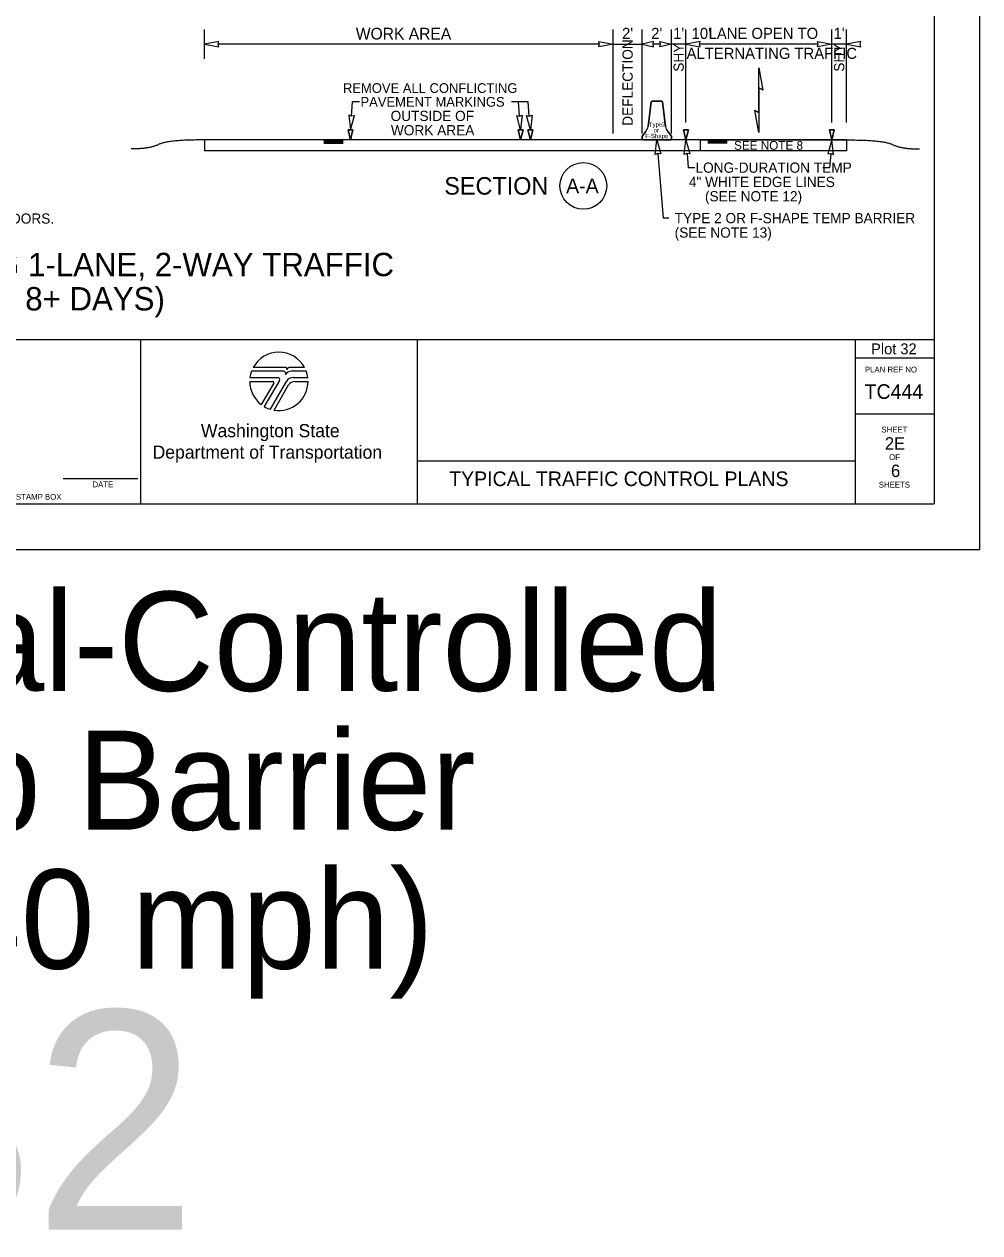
# Model space of a CAD drawing. Extents: x 99976 to 100136, y 99905 to 100011.
# Drawn here: x 100029.51 to 100036.06, y 99905.01 to 99913.29 of the extents above; entities that cross this region are included whole.
import ezdxf

# ---------------------------------------------------------------- set-up
doc = ezdxf.new("R2010")
doc.units = 0
for name, color, linetype in [('SH_DE_DetailHeading1Text', 7, 'Continuous'), ('SH_GI_GeneralNotesBodyText', 7, 'Continuous'), ('SH_GI_PlotLimits', 7, 'Continuous'), ('SH_GI_SheetBorder', 7, 'Continuous'), ('SH_GI_SheetLocationText', 7, 'Continuous'), ('SH_GI_SheetTextInCells', 7, 'Continuous'), ('SH_GI_TitleBlockText', 7, 'Continuous'), ('SH_GI_WSDOTLogo', 7, 'Continuous'), ('TR_WZ_BarrierDoubleFaceElev', 7, 'Continuous'), ('TR_WZ_WorkZoneDetails', 7, 'Continuous'), ('TR_WZ_WorkZoneTextCurrent', 7, 'Continuous')]:
    doc.layers.add(name, color=color, linetype=linetype)

msp = doc.modelspace()

# ---------------------------------------------------------------- linework, layer by layer
at = {"layer": 'SH_GI_PlotLimits'}
msp.add_lwpolyline([(100019.0625, 99909.6875), (100036.0625, 99909.6875), (100036.0625, 99920.6875), (100019.0625, 99920.6875)], close=True, dxfattribs=at)
at = {"layer": 'SH_GI_SheetBorder'}
for p, q in [((100035.75, 99920.375), (100035.75, 99910)), ((100020, 99911.1259), (100035.75, 99911.1259)), ((100030.3089, 99911.1259), (100030.3089, 99910)), ((100032.2055, 99911.1259), (100032.2055, 99910)), ((100035.2079, 99911.1259), (100035.2079, 99910)), ((100035.2079, 99911.0008), (100035.75, 99911.0008)), ((100035.2079, 99910.6176), (100035.75, 99910.6176)), ((100032.2055, 99910.2955), (100035.2079, 99910.2955)), ((100029.7797, 99910.1733), (100030.2914, 99910.1733)), ((100020, 99910), (100035.75, 99910))]:
    msp.add_line(p, q, dxfattribs=at)
at = {"layer": 'SH_GI_WSDOTLogo'}
for p, q in [((100031.059, 99910.8661), (100031.2496, 99910.8661)), ((100031.2894, 99910.9094), (100031.0697, 99910.9094)), ((100031.303, 99910.9354), (100031.0815, 99910.9354)), ((100031.433, 99910.9354), (100031.3351, 99910.9354)), ((100031.343, 99910.9094), (100031.3429, 99910.9094)), ((100031.4448, 99910.9094), (100031.343, 99910.9094)), ((100031.3558, 99910.8661), (100031.4555, 99910.8661)), ((100031.0572, 99910.84), (100031.2148, 99910.84)), ((100031.222, 99910.8277), (100031.1364, 99910.6807)), ((100031.261, 99910.8464), (100031.1567, 99910.6672)), ((100031.1989, 99910.6487), (100031.3089, 99910.839)), ((100031.2244, 99910.6428), (100031.3242, 99910.8156)), ((100031.3655, 99910.8394), (100031.4572, 99910.8394))]:
    msp.add_line(p, q, dxfattribs=at)
for centre, radius, start, end in [((100031.2572, 99910.84), 0.2, 28.47865, 151.53204), ((100031.2572, 99910.84), 0.2, 159.69598, 172.50569), ((100031.2497, 99910.853), 0.0131, 329.76834, 90), ((100031.2894, 99910.8946), 0.0148, 327.8418, 89.99855), ((100031.3429, 99910.861), 0.0484, 89.99529, 147.82376), ((100031.303, 99910.9263), 0.00903, 329.87418, 90.00328), ((100031.3558, 99910.8119), 0.0542, 90, 149.99738), ((100031.3352, 99910.9066), 0.0287, 90.00721, 148.16763), ((100031.2572, 99910.84), 0.2, 7.49431, 20.29406), ((100031.2572, 99910.84), 0.2, 179.99864, 232.84327), ((100031.2149, 99910.8318), 0.0082, 329.74356, 90), ((100031.2572, 99910.84), 0.2, 260.54554, 359.80857), ((100031.3654, 99910.7918), 0.0476, 90, 150.05432), ((100031.2572, 99910.84), 0.2, 239.79292, 253.0448)]:
    msp.add_arc(centre, radius, start, end, dxfattribs=at)
at = {"layer": 'TR_WZ_BarrierDoubleFaceElev'}
for p, q in [((100033.8083, 99912.7548), (100033.8145, 99912.761)), ((100033.8145, 99912.761), (100033.8083, 99912.7548)), ((100033.8145, 99912.761), (100033.8812, 99912.761)), ((100033.8812, 99912.761), (100033.8145, 99912.761)), ((100033.8812, 99912.761), (100033.8875, 99912.7548)), ((100033.8875, 99912.7548), (100033.8812, 99912.761)), ((100033.7885, 99912.586), (100033.8083, 99912.7548)), ((100033.8083, 99912.7548), (100033.7885, 99912.586)), ((100033.8875, 99912.7548), (100033.9073, 99912.586)), ((100033.9073, 99912.586), (100033.8875, 99912.7548)), ((100033.7479, 99912.5194), (100033.7729, 99912.5527)), ((100033.7729, 99912.5527), (100033.7479, 99912.5194)), ((100033.7479, 99912.5006), (100033.7479, 99912.5194)), ((100033.7479, 99912.5194), (100033.7479, 99912.5006)), ((100033.9229, 99912.5527), (100033.9479, 99912.5194)), ((100033.9479, 99912.5194), (100033.9229, 99912.5527)), ((100033.9479, 99912.5194), (100033.9479, 99912.5006)), ((100033.9479, 99912.5006), (100033.9479, 99912.5194)), ((100033.7541, 99912.4944), (100033.7479, 99912.5006)), ((100033.7479, 99912.5006), (100033.7541, 99912.4944)), ((100033.9416, 99912.4944), (100033.7541, 99912.4944)), ((100033.7541, 99912.4944), (100033.9416, 99912.4944)), ((100033.9479, 99912.5006), (100033.9416, 99912.4944)), ((100033.9416, 99912.4944), (100033.9479, 99912.5006))]:
    msp.add_line(p, q, dxfattribs=at)
for centre, start, end in [((100033.7071, 99912.6039), 322.1243, 347.64603), ((100033.7071, 99912.6039), 322.1243, 347.64603), ((100033.9887, 99912.6039), 192.35397, 217.8757), ((100033.9887, 99912.6039), 192.35397, 217.8757)]:
    msp.add_arc(centre, 0.0833, start, end, dxfattribs=at)
at = {"layer": 'TR_WZ_WorkZoneDetails'}
for p, q in [((100030.7479, 99913.0504), (100030.7479, 99913.2504)), ((100033.5479, 99912.5394), (100033.5479, 99913.2504)), ((100033.7479, 99912.5394), (100033.7479, 99913.2504)), ((100033.9479, 99912.5394), (100033.9479, 99913.2504)), ((100034.0479, 99912.6142), (100034.0479, 99913.2504)), ((100035.0479, 99912.6142), (100035.0479, 99913.2504)), ((100035.1479, 99912.6142), (100035.1479, 99913.2504)), ((100033.4542, 99913.1504), (100030.8416, 99913.1504)), ((100033.5479, 99913.1504), (100033.7479, 99913.1504)), ((100033.8729, 99913.1504), (100033.8229, 99913.1504)), ((100034.0479, 99913.1504), (100033.9479, 99913.1504)), ((100034.9542, 99913.1504), (100034.1416, 99913.1504)), ((100035.1479, 99913.1504), (100035.0479, 99913.1504)), ((100034.5479, 99912.8508), (100034.5479, 99912.682)), ((100034.5479, 99912.682), (100034.5479, 99912.8508)), ((100031.7553, 99912.6576), (100031.763, 99912.7552)), ((100031.8092, 99912.7552), (100031.763, 99912.7552)), ((100032.966, 99912.7552), (100032.8531, 99912.7552)), ((100032.9071, 99912.6576), (100032.8993, 99912.7552)), ((100032.9737, 99912.6576), (100032.966, 99912.7552)), ((100030.7479, 99912.4944), (100030.7479, 99912.4194)), ((100035.1479, 99912.4944), (100030.7479, 99912.4944)), ((100031.5649, 99912.4891), (100031.6979, 99912.4891)), ((100031.5649, 99912.4835), (100031.6979, 99912.4835)), ((100031.5649, 99912.4779), (100031.6979, 99912.4779)), ((100031.5649, 99912.4726), (100031.6979, 99912.4726)), ((100034.3309, 99912.4887), (100034.1979, 99912.4887)), ((100034.3309, 99912.4831), (100034.1979, 99912.4831)), ((100034.3309, 99912.4774), (100034.1979, 99912.4774)), ((100034.3309, 99912.4722), (100034.1979, 99912.4722)), ((100035.1479, 99912.4944), (100035.1479, 99912.4194)), ((100035.1479, 99912.4194), (100030.7479, 99912.4194)), ((100033.8553, 99912.4009), (100033.8906, 99911.9574)), ((100034.0553, 99912.4009), (100034.0631, 99912.3034)), ((100035.0404, 99912.4009), (100035.0327, 99912.3034)), ((100034.1092, 99912.3034), (100034.0631, 99912.3034)), ((100035.0327, 99912.3034), (100034.9865, 99912.3034)), ((100033.9306, 99911.9574), (100033.8906, 99911.9574))]:
    msp.add_line(p, q, dxfattribs=at)
for points in [[(100030.7479, 99913.1504), (100030.8461, 99913.1312), (100030.8416, 99913.1504), (100030.8461, 99913.1697)], [(100033.5479, 99913.1504), (100033.4496, 99913.1312), (100033.4542, 99913.1504), (100033.4496, 99913.1697)], [(100033.7479, 99913.1504), (100033.8265, 99913.1312), (100033.8229, 99913.1504), (100033.8265, 99913.1697)], [(100033.9479, 99913.1504), (100033.8693, 99913.1312), (100033.8729, 99913.1504), (100033.8693, 99913.1697)], [(100034.0479, 99913.1504), (100034.1462, 99913.1312), (100034.1416, 99913.1504), (100034.1462, 99913.1697)], [(100035.0479, 99913.1504), (100034.9496, 99913.1312), (100034.9542, 99913.1504), (100034.9496, 99913.1697)], [(100035.1479, 99913.1504), (100035.2462, 99913.1312), (100035.2416, 99913.1504), (100035.2462, 99913.1697)], [(100034.5479, 99912.9884), (100034.5749, 99912.8352), (100034.5479, 99912.8508)], [(100034.5479, 99912.5444), (100034.5209, 99912.6976), (100034.5479, 99912.682)], [(100031.7478, 99912.5642), (100031.7748, 99912.6606), (100031.7552, 99912.6576), (100031.7363, 99912.6637)], [(100032.9145, 99912.5642), (100032.8875, 99912.6606), (100032.9071, 99912.6576), (100032.926, 99912.6637)], [(100032.9812, 99912.5642), (100032.9542, 99912.6606), (100032.9738, 99912.6576), (100032.9926, 99912.6637)], [(100031.7479, 99912.4944), (100031.7312, 99912.5642), (100031.7645, 99912.5642)], [(100032.9145, 99912.4944), (100032.8978, 99912.5642), (100032.9312, 99912.5642)], [(100032.9812, 99912.4944), (100032.9645, 99912.5642), (100032.9978, 99912.5642)], [(100034.0479, 99912.4944), (100034.0312, 99912.5642), (100034.0645, 99912.5642)], [(100035.0479, 99912.4944), (100035.0312, 99912.5642), (100035.0645, 99912.5642)], [(100033.8479, 99912.4944), (100033.8748, 99912.3979), (100033.8553, 99912.4009), (100033.8364, 99912.3949)], [(100034.0479, 99912.4944), (100034.0748, 99912.3979), (100034.0553, 99912.4009), (100034.0364, 99912.3949)], [(100034.1479, 99912.4944), (100035.1479, 99912.4944), (100035.1479, 99912.4194), (100034.1479, 99912.4194)], [(100034.1479, 99912.4944), (100035.1479, 99912.4944), (100035.1479, 99912.4194), (100034.1479, 99912.4194)], [(100035.0479, 99912.4944), (100035.0209, 99912.3979), (100035.0405, 99912.4009), (100035.0593, 99912.3949)]]:
    msp.add_lwpolyline(points, close=True, dxfattribs=at)
for points in [[(100031.7645, 99912.5642), (100031.7312, 99912.5642), (100031.7479, 99912.4944), (100031.7645, 99912.5642)], [(100032.9312, 99912.5642), (100032.8978, 99912.5642), (100032.9145, 99912.4944), (100032.9312, 99912.5642)], [(100032.9978, 99912.5642), (100032.9645, 99912.5642), (100032.9812, 99912.4944), (100032.9978, 99912.5642)], [(100034.0645, 99912.5642), (100034.0312, 99912.5642), (100034.0479, 99912.4944), (100034.0645, 99912.5642)], [(100035.0645, 99912.5642), (100035.0312, 99912.5642), (100035.0479, 99912.4944), (100035.0645, 99912.5642)]]:
    msp.add_lwpolyline(points, dxfattribs=at)
msp.add_circle((100033.3444, 99912.1794), 0.16, dxfattribs=at)
for points in [[(100030.7479, 99912.4944), (100030.4967, 99912.4944), (100030.3712, 99912.4322), (100030.2457, 99912.4322)], [(100035.1479, 99912.4944), (100035.399, 99912.4945), (100035.5245, 99912.4324), (100035.65, 99912.4325)]]:
    msp.add_open_spline(points, degree=2, dxfattribs=at)

# ---------------------------------------------------------------- texts
at = {"layer": 'SH_DE_DetailHeading1Text'}
for s, p in [('ADVANCED TEMPORARY SIGNAL-CONTROLLED ALTERNATING 1-LANE, 2-WAY TRAFFIC', (100022.9401, 99911.5606)), ('35 WZSL + TEMP BARRIER (40 MPH HIGHWAYS, 8+ DAYS)', (100024.5313, 99911.3259))]:
    msp.add_text(s, height=0.16, rotation=360, dxfattribs=at).set_placement(p)
at = {"layer": 'SH_GI_GeneralNotesBodyText'}
msp.add_text('ROADWAY WIDTH RESTRICTIONS. 30 DAY NOTICE REQUIRED ON MAJOR FREIGHT CORRIDORS.', height=0.07, rotation=360, dxfattribs=at).set_placement((100025.3222, 99911.9206))
at = {"layer": 'SH_GI_SheetBorder'}
msp.add_text('PLAN REF NO', height=0.040032, dxfattribs=at).set_placement((100035.2747, 99910.9008))
at = {"layer": 'SH_GI_SheetLocationText'}
for s, height, p in [('Plot 32', 0.075, (100035.3171, 99911.025)), (' Temp Signal-Controlled', 0.68, (100024.4951, 99908.7191)), ('Alt Traffic w/ Temp Barrier', 0.68, (100022.0459, 99907.7671)), ('& Rumble Strips (40 mph)', 0.68, (100021.8582, 99906.8151)), ('Plot 32', 1.5, (100024.4483, 99905.0267))]:
    msp.add_text(s, height=height, dxfattribs=at).set_placement(p)
at = {"layer": 'SH_GI_SheetTextInCells'}
for s, height, p in [('Washington State', 0.090072, (100030.7229, 99910.4571)), ('SHEET', 0.04003, (100035.3877, 99910.4896)), ('Department of Transportation', 0.090072, (100030.3916, 99910.3101)), ('OF', 0.04003, (100035.4406, 99910.3008)), ('DATE', 0.04003, (100029.9794, 99910.1141)), ('SHEETS', 0.04003, (100035.3698, 99910.112)), ('P.E. STAMP BOX', 0.040032, (100029.339, 99910.0286))]:
    msp.add_text(s, height=height, dxfattribs=at).set_placement(p)
at = {"layer": 'SH_GI_TitleBlockText'}
for s, height, p in [('TC444', 0.1, (100035.2728, 99910.72)), ('2E', 0.085, (100035.4116, 99910.3723)), ('TYPICAL TRAFFIC CONTROL PLANS', 0.1, (100032.4251, 99910.1224)), ('6', 0.085, (100035.4534, 99910.1843))]:
    msp.add_text(s, height=height, dxfattribs=at).set_placement(p)
at = {"layer": 'TR_WZ_BarrierDoubleFaceElev'}
for s, p in [('Type', (100033.7937, 99912.5853)), ('2', (100033.8828, 99912.5853)), ('F-Shape', (100033.7684, 99912.506)), ('or', (100033.8264, 99912.5456))]:
    msp.add_text(s, height=0.03, dxfattribs=at).set_placement(p)
at = {"layer": 'TR_WZ_WorkZoneDetails'}
for s, height, p in [('WORK AREA', 0.08, (100031.785, 99913.1824)), ("2'", 0.076, (100033.6099, 99913.1864)), ("2'", 0.076, (100033.8095, 99913.1864)), ("1'", 0.076, (100033.9599, 99913.1864)), ("10'", 0.076, (100034.0867, 99913.1864)), (' LANE OPEN TO', 0.076, (100034.1748, 99913.1864)), ("1'", 0.076, (100035.0595, 99913.1864)), ('ALTERNATING TRAFFIC', 0.076, (100034.0522, 99913.0496))]:
    msp.add_text(s, height=height, dxfattribs=at).set_placement(p)
for s, height, rotation, p in [('DEFLECTION', 0.07, 90, (100033.6829, 99912.591)), ('SHY', 0.07, 90, (100034.0329, 99912.9617)), ('SHY', 0.07, 90, (100035.1329, 99912.9617)), ('SECTION', 0.12, 360, (100032.3913, 99912.1194)), ('A-A', 0.1, 360, (100033.2265, 99912.1294))]:
    msp.add_text(s, height=height, rotation=rotation, dxfattribs=at).set_placement(p)
at = {"layer": 'TR_WZ_WorkZoneTextCurrent'}
for s, height, p in [('REMOVE ALL CONFLICTING', 0.0665, (100031.6969, 99912.8164)), ('PAVEMENT MARKINGS', 0.0665, (100031.8168, 99912.7219)), ('OUTSIDE OF', 0.07, (100032.0233, 99912.6239)), ('WORK AREA', 0.07, (100032.0253, 99912.5259)), ('SEE NOTE 8', 0.06, (100034.3778, 99912.4269)), ('LONG-DURATION TEMP', 0.07, (100034.1132, 99912.2694)), ('4" WHITE EDGE LINES', 0.07, (100034.068, 99912.1714)), ('(SEE NOTE 12)', 0.07, (100034.1784, 99912.0734)), ('TYPE 2 OR F-SHAPE TEMP BARRIER', 0.07, (100033.9706, 99911.9234)), ('(SEE NOTE 13)', 0.07, (100033.9706, 99911.8246))]:
    msp.add_text(s, height=height, dxfattribs=at).set_placement(p)

doc.saveas('drawing.dxf')
